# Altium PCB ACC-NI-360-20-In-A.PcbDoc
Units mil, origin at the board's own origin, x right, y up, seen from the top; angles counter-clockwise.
Board outline 1500 x 3250 mil, 2 copper layers (Top Layer, Bottom Layer), stack 22.756 mil thick; 18 components, 5 nets, 48 pads, 384 vias.
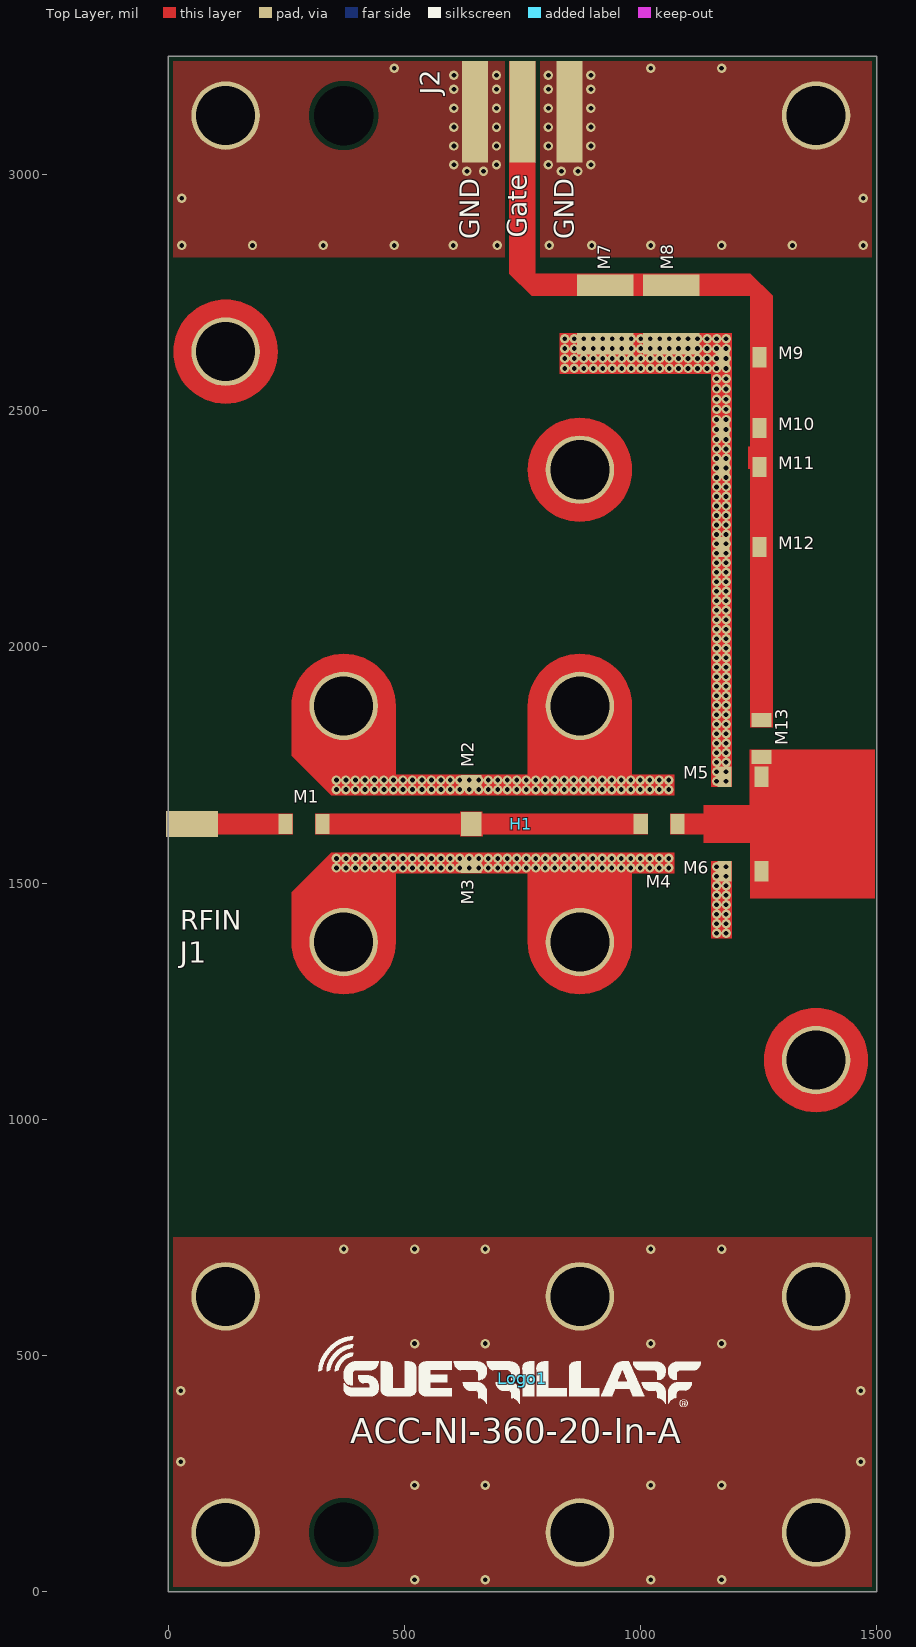
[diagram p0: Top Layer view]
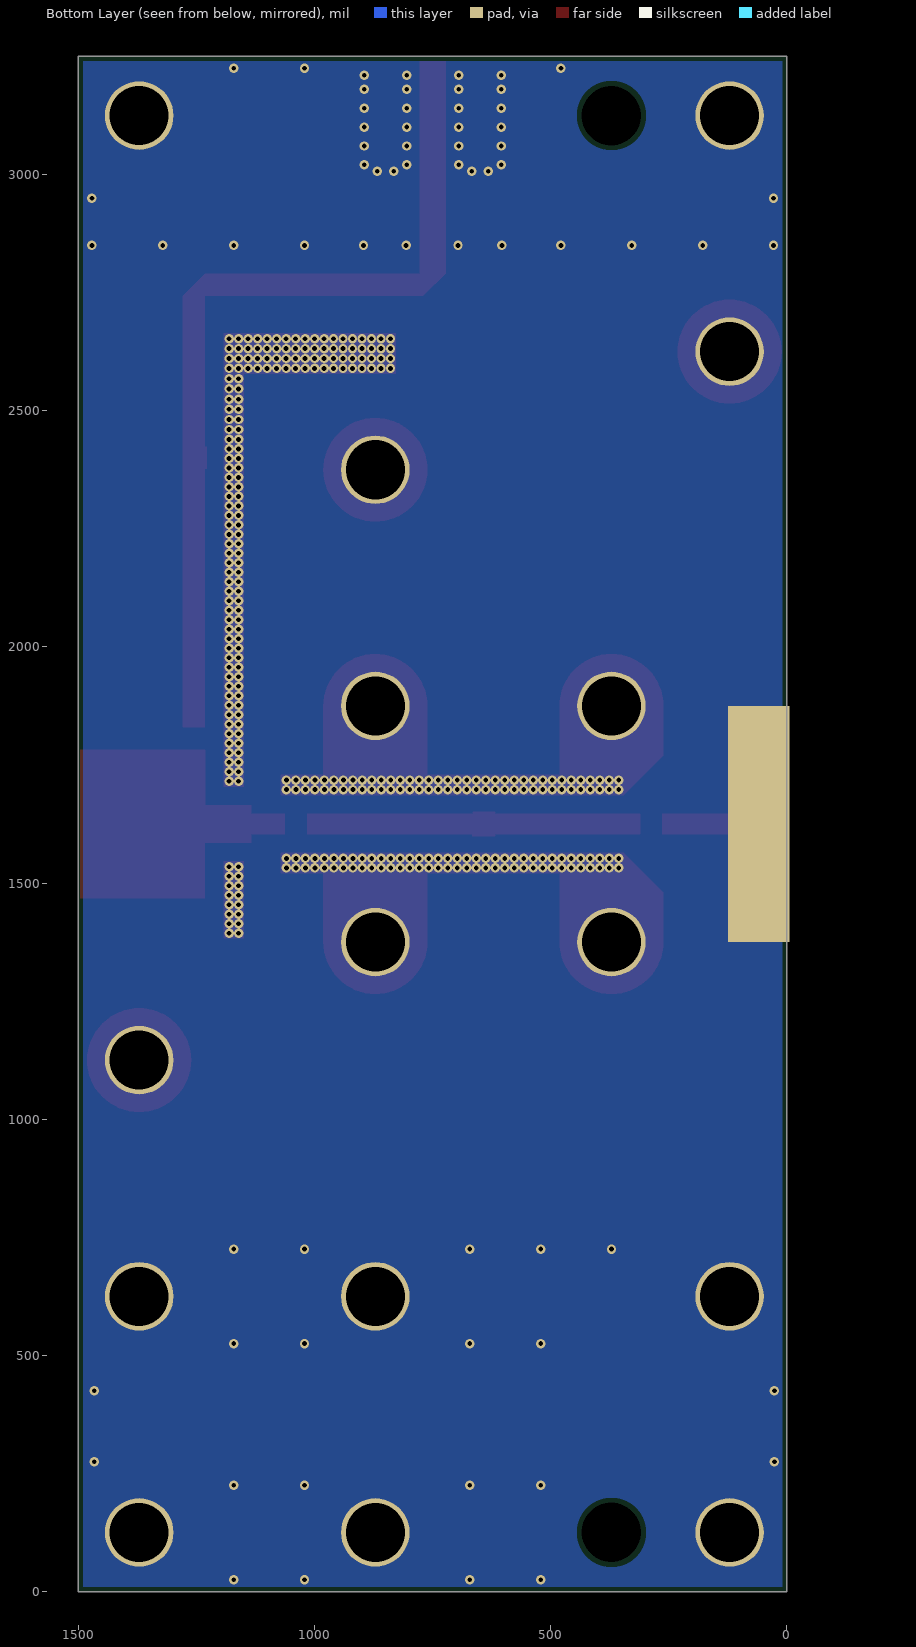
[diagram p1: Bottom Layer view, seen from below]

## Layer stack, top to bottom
Top Layer: signal copper 1.378
Dielectric 1: prepreg 20, RO4350B, Dk 3.48
Bottom Layer: signal copper 1.378

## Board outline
0,0 0,3250 1500,3250 1500,0

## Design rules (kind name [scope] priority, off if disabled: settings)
BackDrilling [IsVia and not InNet('GND')] p1: maxstublength=5 usetopbackdrill=TRUE usebottombackdrill=TRUE holeoversize=10 holetolplus=0.2 holetolminus=0.2
BoardOutlineClearance BoardOutlineClearance_Solder_Mask [OnLayer('Top Solder') Or OnLayer('Bottom Solder')] p1: gap=0 ignorepadtopadclearanceinfootprint=FALSE
BoardOutlineClearance [All] p2: gap=10 ignorepadtopadclearanceinfootprint=FALSE
Clearance Clearance_I/O [InNetClass('I/O') vs InNet('GND')] p1: gap=7 ignorepadtopadclearanceinfootprint=TRUE
Clearance Clearance_RF_Strip [InNetClass('RF_Strip') vs InNet('GND')] p2: gap=40 ignorepadtopadclearanceinfootprint=TRUE
Clearance Clearance_RF_15-15-8 [InNetClass('RF_15-15-8') vs InNet('GND')] p3: gap=15 ignorepadtopadclearanceinfootprint=TRUE
Clearance Clearance_RF_20-10-12 [InNetClass('RF_20-10-12') vs InNet('GND')] p4: gap=10 ignorepadtopadclearanceinfootprint=TRUE
Clearance Clearance_RF_30-20-16 [InNetClass('RF_30-20-16') vs InNet('GND')] p5: gap=20 ignorepadtopadclearanceinfootprint=TRUE
Clearance Clearance_RF_28-21-16_FR4 [InNetClass('RF_28-21-16_FR4') vs InNet('GND')] p6: gap=21 ignorepadtopadclearanceinfootprint=TRUE
Clearance Clearance_RF_15-27p5-8 [InNetClass('RF_15-27p5-8') vs InNet('GND')] p7: gap=27.5 ignorepadtopadclearanceinfootprint=TRUE
Clearance Clearance_RF_25-22-40_75ohm [InNetClass('RF_25-22-40_75ohm') vs InNet('GND')] p8: gap=22 ignorepadtopadclearanceinfootprint=TRUE
Clearance Clearance_GND [InNet('GND')] p9: gap=10 ignorepadtopadclearanceinfootprint=TRUE
Clearance [All] p10: gap=6 ignorepadtopadclearanceinfootprint=TRUE
ComponentClearance ComponentClearance_Heatsink [InComponent('All') And OnLayer('Top Layer') vs HasFootprint('Heatsink_wFid')] p1: gap=0 collisioncheckmode=3 verticalgap=0 showdistances=FALSE
ComponentClearance ComponentClearance_PCB_Frame [InComponent('All') And OnLayer('Top Layer') vs HasFootprint('PCB_Frame')] p2: gap=0 collisioncheckmode=3 verticalgap=0 showdistances=FALSE
ComponentClearance [All] p3: gap=10 collisioncheckmode=3 verticalgap=10 showdistances=TRUE
HoleSize [All] p1: absolutevalues=TRUE maxlimit=200 minlimit=8 maxpercent=80.000 minpercent=20.000
MinimumSolderMaskSliver [All] p1: minsoldermaskwidth=5
PlaneClearance [Not InNet('GND')] p1: clearance=20
PlaneConnect [InNet('GND')] p1: planeconnectstyle=Direct reliefexpansion=20 reliefentries=4 reliefconductorwidth=10 reliefairgap=10
PolygonConnect [All vs InNet('GND')] p1: connectstyle=Direct reliefconductorwidth=10 reliefentries=4 polygonreliefangle="90 Angle" airgapwidth=10
RoutingVias [All] p1: holewidth=10 width=20 viastyle="Through Hole" minholewidth=8 minwidth=18 maxholewidth=23.62 maxwidth=33.62
SilkToSilkClearance [All] p1: silktosilkclearance=5
SilkToSolderMaskClearance [IsPad] p1: minsilkscreentomaskgap=5 clearancetoexposedcopper=TRUE
SolderMaskExpansion [All] p1: expansion=1 istentingtop=FALSE
UnRoutedNet [All] p1: checkbadconnections=TRUE
Width [All] p1: maxlimit=100 minlimit=6 preferedwidth=10
22 further rules are at their usual default settings.

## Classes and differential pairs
component class ACC-NI-360-20-In-A: H1 J1 J2 Logo1 M1 M2 M3 M4 M5 M6 M7 M8 M9 M10 M11 M12 M13
net class RF_Strip: NetJ1_1 NetM1_1 NetM4_1

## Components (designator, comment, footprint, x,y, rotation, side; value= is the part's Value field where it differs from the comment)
F66 "Comment" PCB_Fab_30T-20G-16D_4003 -723.18,126.8 r0 top locked
H1 "Cooling_Block_Grid" Cooling_Block_Grid 1871.5,1625 r0 top locked
J1 "SMA Panel Mount_RevB" "SMA Panel Mount_RevB" 0,1625 r0 top
J2 "Header_H_3-Pin_100mil" Header_H_3-Pin_100mil 750,3250 r0 top
Logo1 "GRF_2021_Full" GRF_2021_Full 750,450 r0 top
M1 "0805_30x70x42" 0805_30x70x42#1 287.4,1625 r180 top
M2 "0805_30x70x42" 0805_30x70x42#1 641.73,1674.31 r270 top
M3 "0805_30x70x42" 0805_30x70x42#1 641.73,1575.69 r90 top
M4 "0805_30x70x42" 0805_30x70x42#1 1039.37,1625 r180 top
M5 "0805_30x70x42" 0805_30x70x42#2 1216.91,1725.24 r0 top
M6 "0805_30x70x42" 0805_30x70x42#2 1216.91,1524.76 r0 top
M7 "1210_45x120x75" 1210_45x120x75 925.04,2703.68 r90 top
M8 "1210_45x120x75" 1210_45x120x75 1064.96,2703.68 r90 top
M9 "0805_30x70x42" 0805_30x70x42#1 1212.6,2613.19 r0 top
M10 "0805_30x70x42" 0805_30x70x42#1 1212.6,2463.58 r0 top
M11 "0805_30x70x42" 0805_30x70x42#1 1212.6,2380.91 r0 top
M12 "0805_30x70x42" 0805_30x70x42#1 1212.6,2211.61 r0 top
M13 "0805_30x70x42" 0805_30x70x42#1 1255.91,1806.1 r90 top

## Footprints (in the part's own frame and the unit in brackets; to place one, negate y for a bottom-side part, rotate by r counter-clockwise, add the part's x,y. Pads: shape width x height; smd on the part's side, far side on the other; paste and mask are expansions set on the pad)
0805_30x70x42#1 [mil] "Generic 0805 SMD"
  rect 30x43 smd: 1(-39,0) 2(39,0)
0805_30x70x42#2 [mil] "Generic 0805 SMD"
  rect 30x43 smd: 1(-39,0)
  rect 30x43 smd mask+1: 2(39,0)
1210_45x120x75 [mil] "Generic 1210 SMD"
  rect 45x120 smd: 1(-62,0) 2(62,0)
Cooling_Block_Grid [mil] "Heatsink Mounting Holes"
  round 145 hole 125 paste-100 mask+37.5: 1(-1750,-1500) 1(-1750,-1000) 1(-1750,1000) 1(-1750,1500) 1(-1500,-250) 1(-1500,250) 1(-1000,-1500) 1(-1000,-1000) 1(-1000,-250) 1(-1000,250) 1(-1000,750) 1(-500,-1500) 1(-500,-1000) 1(-500,-500) 1(-500,1500)
  round 0 hole 125.98 unplated paste-100 mask+20: 2(-1500,-1500) 2(-1500,1500)
GRF_2021_Full [mil] "2021 Guerrilla RF Logo"
  silkscreen extent -432,-59 378,90
Header_H_3-Pin_100mil [mil] "Generic Flat Header"
  rect 55x215 smd paste-28: 1(-100,-117.5) 2(0,-117.5) 3(100,-117.5)
PCB_Fab_30T-20G-16D_4003 [mil] "STD RF&Stack  30mil RF 20mil Gap  16mil Dielectric"
"SMA Panel Mount_RevB" [mil] "901-2GB100000AE"
  rect 110x55 smd paste-50: 1(50,0)
  rect 130x500 smd far side paste-50: 2(60,0)

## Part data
H1: library part "Mounting Holes"
J1: library part RF_Conn
J2: library part Header_3-Pin, "Header 3-Pin"
Logo1: library part GRF_Logo, "=CurrentFootprint"
M1 M2 M3 M4 M5 M6 M7 M8 M9 M10 M11 M12: library part Capacitor
M13: library part Resistor

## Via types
v1: diameter 20/20 (per signal layer), hole 10, Top Layer to Bottom Layer, tented top, 318 vias
v2: diameter 20/20 (per signal layer), hole 10, Top Layer to Bottom Layer, 66 vias

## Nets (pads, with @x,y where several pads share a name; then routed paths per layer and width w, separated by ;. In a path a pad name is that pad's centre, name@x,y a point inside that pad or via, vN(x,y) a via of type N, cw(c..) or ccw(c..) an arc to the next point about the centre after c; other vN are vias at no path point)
GND: H1.1 J1.2 J2.1 J2.3 M2.1 M3.1 M5.1 M6.1 M7.1 M8.1 M9.1 M10.1 M11.1 M12.1
  other v1: 1161,1393.75 1181.1,1393.75 1161,1413.85 1181.1,1413.85 1161,1433.95 1181.1,1433.95 1161,1454.05 1181.1,1454.05 1161,1474.15 1181.1,1474.15 1161,1494.25 1181.1,1494.25 1161,1514.35 1181.1,1514.35 356.2,1532.07 376.3,1532.07 396.4,1532.07 416.5,1532.07 436.6,1532.07 456.7,1532.07 476.8,1532.07 496.9,1532.07 517,1532.07 537.1,1532.07 557.2,1532.07 577.3,1532.07 597.4,1532.07 617.5,1532.07 637.6,1532.07 657.7,1532.07 677.8,1532.07 697.9,1532.07 718,1532.07 738.1,1532.07 758.2,1532.07 778.3,1532.07 798.4,1532.07 818.5,1532.07 838.6,1532.07 858.7,1532.07 878.8,1532.07 898.9,1532.07 919,1532.07 939.1,1532.07 959.2,1532.07 979.3,1532.07 999.4,1532.07 1019.5,1532.07 1039.6,1532.07 1059.7,1532.07 1161,1534.45 1181.1,1534.45 356.2,1552.17 376.3,1552.17 396.4,1552.17 416.5,1552.17 436.6,1552.17 456.7,1552.17 476.8,1552.17 496.9,1552.17 517,1552.17 537.1,1552.17 557.2,1552.17 577.3,1552.17 597.4,1552.17 617.5,1552.17 637.6,1552.17 657.7,1552.17 677.8,1552.17 697.9,1552.17 718,1552.17 738.1,1552.17 758.2,1552.17 778.3,1552.17 798.4,1552.17 818.5,1552.17 838.6,1552.17 858.7,1552.17 878.8,1552.17 898.9,1552.17 919,1552.17 939.1,1552.17 959.2,1552.17 979.3,1552.17 999.4,1552.17 1019.5,1552.17 1039.6,1552.17 1059.7,1552.17 356.2,1697.83 376.3,1697.83 396.4,1697.83 416.5,1697.83 436.6,1697.83 456.7,1697.83 476.8,1697.83 496.9,1697.83 517,1697.83 537.1,1697.83 557.2,1697.83 577.3,1697.83 597.4,1697.83 617.5,1697.83 637.6,1697.83 657.7,1697.83 677.8,1697.83 697.9,1697.83 718,1697.83 738.1,1697.83 758.2,1697.83 778.3,1697.83 798.4,1697.83 818.5,1697.83 838.6,1697.83 858.7,1697.83 878.8,1697.83 898.9,1697.83 919,1697.83 939.1,1697.83 959.2,1697.83 979.3,1697.83 999.4,1697.83 1019.5,1697.83 1039.6,1697.83 1059.7,1697.83 1161,1715.55 1181.1,1715.55 356.2,1717.93 376.3,1717.93 396.4,1717.93 416.5,1717.93 436.6,1717.93 456.7,1717.93 476.8,1717.93 496.9,1717.93 517,1717.93 537.1,1717.93 557.2,1717.93 577.3,1717.93 597.4,1717.93 617.5,1717.93 637.6,1717.93 657.7,1717.93 677.8,1717.93 697.9,1717.93 718,1717.93 738.1,1717.93 758.2,1717.93 778.3,1717.93 798.4,1717.93 818.5,1717.93 838.6,1717.93 858.7,1717.93 878.8,1717.93 898.9,1717.93 919,1717.93 939.1,1717.93 959.2,1717.93 979.3,1717.93 999.4,1717.93 1019.5,1717.93 1039.6,1717.93 1059.7,1717.93 1161,1735.65 1181.1,1735.65 1161,1755.75 1181.1,1755.75 1161,1775.85 1181.1,1775.85 1161,1795.95 1181.1,1795.95 1161,1816.05 1181.1,1816.05 1161,1836.15 1181.1,1836.15 1161,1856.25 1181.1,1856.25 1161,1876.35 1181.1,1876.35 1161,1896.45 1181.1,1896.45 1161,1916.55 1181.1,1916.55 1161,1936.65 1181.1,1936.65 1161,1956.75 1181.1,1956.75 1161,1976.85 1181.1,1976.85 1161,1996.95 1181.1,1996.95 1161,2017.05 1181.1,2017.05 1161,2037.15 1181.1,2037.15 1161,2057.25 1181.1,2057.25 1161,2077.35 1181.1,2077.35 1161,2097.45 1181.1,2097.45 1161,2117.55 1181.1,2117.55 1161,2137.65 1181.1,2137.65 1161,2157.75 1181.1,2157.75 1161,2177.85 1181.1,2177.85 1161,2197.95 1181.1,2197.95 1161,2218.05 1181.1,2218.05 1161,2238.15 1181.1,2238.15 1161,2258.25 1181.1,2258.25 1161,2278.35 1181.1,2278.35 1161,2298.45 1181.1,2298.45 1161,2318.55 1181.1,2318.55 1161,2338.65 1181.1,2338.65 1161,2358.75 1181.1,2358.75 1161,2378.85 1181.1,2378.85 1161,2398.95 1181.1,2398.95 1161,2419.05 1181.1,2419.05 1161,2439.15 1181.1,2439.15 1161,2460.25 1181.1,2460.25 1161,2481.35 1181.1,2481.35 1161,2502.95 1181.1,2502.95 1161,2524.55 1181.1,2524.55 1161,2546.15 1181.1,2546.15 1161,2567.75 1181.1,2567.75 839.4,2589.57 859.5,2589.57 879.6,2589.57 899.7,2589.57 919.8,2589.57 939.9,2589.57 960,2589.57 980.1,2589.57 1000.2,2589.57 1020.3,2589.57 1040.4,2589.57 1060.5,2589.57 1080.6,2589.57 1100.7,2589.57 1120.8,2589.57 1140.9,2589.57 1161,2589.57 1181.1,2589.57 839.4,2610.56 859.5,2610.56 879.6,2610.56 899.7,2610.56 919.8,2610.56 939.9,2610.56 960,2610.56 980.1,2610.56 1000.2,2610.56 1020.3,2610.56 1040.4,2610.56 1060.5,2610.56 1080.6,2610.56 1100.7,2610.56 1120.8,2610.56 1140.9,2610.56 1161,2610.56 1181.1,2610.56 839.4,2631.56 859.5,2631.56 879.6,2631.56 899.7,2631.56 919.8,2631.56 939.9,2631.56 960,2631.56 980.1,2631.56 1000.2,2631.56 1020.3,2631.56 1040.4,2631.56 1060.5,2631.56 1080.6,2631.56 1100.7,2631.56 1120.8,2631.56 1140.9,2631.56 1161,2631.56 1181.1,2631.56 839.4,2652.56 859.5,2652.56 879.6,2652.56 899.7,2652.56 919.8,2652.56 939.9,2652.56 960,2652.56 980.1,2652.56 1000.2,2652.56 1020.3,2652.56 1040.4,2652.56 1060.5,2652.56 1080.6,2652.56 1100.7,2652.56 1120.8,2652.56 1140.9,2652.56 1161,2652.56 1181.1,2652.56
  other v2: 521.5,25 671.5,25 1021.5,25 1171.5,25 521.5,225 671.5,225 1021.5,225 1171.5,225 26.5,275 1466.5,275 26.5,425 1466.5,425 521.5,525 671.5,525 1021.5,525 1171.5,525 371.5,725 521.5,725 671.5,725 1021.5,725 1171.5,725 28.5,2850 178.5,2850 328.5,2850 478.5,2850 603.5,2850 696.5,2850 806.5,2850 896.5,2850 1021.5,2850 1171.5,2850 1321.5,2850 1471.5,2850 28.5,2950 1471.5,2950 632.5,3007 667.5,3007 832.5,3007 867.5,3007 605,3020.5 695,3020.5 805,3020.5 895,3020.5 605,3060.5 695,3060.5 805,3060.5 895,3060.5 605,3100.5 695,3100.5 805,3100.5 895,3100.5 605,3140.5 695,3140.5 805,3140.5 895,3140.5 605,3180.5 695,3180.5 805,3180.5 895,3180.5 605,3210.5 695,3210.5 805,3210.5 895,3210.5 478.5,3225 1021.5,3225 1171.5,3225
NetJ1_1: J1.1 M1.2
NetJ2_2: J2.2 M7.2 M8.2 M9.2 M10.2 M11.2 M12.2 M13.2
NetM1_1: M1.1 M2.2 M3.2 M4.2
NetM4_1: M4.1 M5.2 M6.2 M13.1
pads on no net: H1.2

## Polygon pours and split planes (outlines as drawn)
GND on Top Layer "NONET_L-01_P-001" (solid, pour order 0): 0,750 1500,750 1500,0 0,0
GND on Top Layer "NONET_L-01_P-001" (solid, pour order 4): 0,3250 1500,3250 1500,2825 0,2825
no net on Bottom Solder "NONET_L-01_P-001" (solid): 0,3250 0,0 1500,0 1500,3250
no net on Top Solder "NONET_L-01_P-001" (solid): 0,3250 0,0 1500,0 1500,3250
GND on Bottom Layer "NONET_L-01_P-001" (solid, pour order 2): 0,3250 0,0 1500,0 1500,3250

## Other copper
Top Layer:
  region net GND: 231.5,2625 ccw(c121.5,2625) 121.5,2735 ccw(c121.5,2625) 11.5,2625 ccw(c121.5,2625) 121.5,2515 ccw(c121.5,2625)
  region net GND: 981.5,2375 ccw(c871.5,2375) 871.5,2485 ccw(c871.5,2375) 761.5,2375 ccw(c871.5,2375) 871.5,2265 ccw(c871.5,2375)
  region net GND: 1371.5,1015 ccw(c1371.5,1125) 1481.5,1125 ccw(c1371.5,1125) 1371.5,1235 ccw(c1371.5,1125) 1261.5,1125 ccw(c1371.5,1125)
  region net GND: 371.5,1485 ccw(c371.5,1375) 261.5,1375 ccw(c371.5,1375) 371.5,1265 ccw(c371.5,1375) 481.5,1375 ccw(c371.5,1375)
  region net GND: 371.5,1985 ccw(c371.5,1875) 261.5,1875 ccw(c371.5,1875) 371.5,1765 ccw(c371.5,1875) 481.5,1875 ccw(c371.5,1875)
  region net GND: 761.5,1875 ccw(c871.5,1875) 871.5,1765 ccw(c871.5,1875) 981.5,1875 ccw(c871.5,1875) 871.5,1985 ccw(c871.5,1875)
  region net GND: 981.5,1375 ccw(c871.5,1375) 871.5,1485 ccw(c871.5,1375) 761.5,1375 ccw(c871.5,1375) 871.5,1265 ccw(c871.5,1375)
  region net GND: 345.5,1686.02 261.5,1770.02 261.5,1875 481.5,1875 481.5,1686.02
  region net GND: 345.5,1563.98 261.5,1479.98 261.5,1375 481.5,1375 481.5,1563.98
  region net GND: 761.5,1875 761.5,1717.93 981.5,1717.93 981.5,1875
  region net GND: 981.5,1375 981.5,1532.07 761.5,1532.07 761.5,1375
  region net NetJ2_2: 722.5,3240 722.5,2790.35 769.74,2743.11 811.5,2743.11 811.5,2790.35 777.5,2790.35 777.5,3240
  region net NetJ2_2: 807.5,2790.35 1232.28,2790.35 1279.53,2743.11 1279.53,1830.1 1232.28,1830.1 1232.28,2376.83 1228.49,2376.83 1228.35,2376.97 1228.35,2424.21 1232.28,2424.21 1232.28,2743.11 807.5,2743.11
  region net GND: 1149.61,1546.26 1149.61,1383 1192.91,1383 1192.91,1546.26
  region net GND: 828.5,2664.37 828.5,2577.76 1149.61,2577.76 1149.61,1865.16 1192.91,1865.16 1192.91,2664.37
  region net GND: 1149.61,1703.74 1149.61,1865.16 1192.91,1865.16 1192.91,1703.74
  region net GND: 345.5,1563.98 1071.51,1563.98 1071.51,1520.67 345.5,1520.67
  region net GND: 345.5,1686.02 1071.51,1686.02 1071.51,1729.33 345.5,1729.33
  region net NetJ1_1: 263.78,1646.5 0,1646.5 0,1603.5 263.78,1603.5
  region net NetM1_1: 1015.75,1646.5 665.35,1646.5 665.35,1650.59 618.11,1650.59 618.11,1646.5 311.02,1646.5 311.02,1603.5 618.11,1603.5 618.11,1599.41 666.34,1599.41 666.34,1603.5 1015.75,1603.5
  region net NetM4_1: 1062.99,1646.5 1133.86,1646.5 1133.86,1664.37 1231.3,1664.37 1231.3,1782.48 1496,1782.48 1496,1467.52 1232.28,1467.52 1232.28,1585.63 1133.86,1585.63 1133.86,1603.5 1062.99,1603.5

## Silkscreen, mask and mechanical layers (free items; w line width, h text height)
Top Overlay:
  text "Gate" at 772.42,2866.01 h70 r90
  text "GND" at 672.42,2863.42 h70 r90
  text "GND" at 872.42,2863.42 h70 r90
  text "RFIN" at 25,1387.58 h70
  text "ACC-NI-360-20-In-A" at 385.06,296.18 h90
Top Solder:
  region: 1271.65,2638.78 1228.35,2638.78 1228.35,2587.6 1271.65,2587.6
  rectangle: 1153.54,2587.6 1196.85,2638.78
  region: 1271.65,2489.17 1228.35,2489.17 1228.35,2437.99 1271.65,2437.99
  rectangle: 1153.54,2437.99 1196.85,2489.17
  region: 1271.65,2406.5 1228.35,2406.5 1228.35,2355.32 1271.65,2355.32
  rectangle: 1153.54,2355.32 1196.85,2406.5
  region: 1271.65,2237.2 1228.35,2237.2 1228.35,2186.02 1271.65,2186.02
  rectangle: 1153.54,2186.02 1196.85,2237.2
  region: 1281.5,1747.05 1281.5,1790.35 1230.32,1790.35 1230.32,1747.05
  region: 1230.32,1865.16 1230.32,1821.85 1281.5,1821.85 1281.5,1865.16
  rectangle: 980.32,1599.41 1023.62,1650.59
  region: 1098.43,1650.59 1055.12,1650.59 1055.12,1599.41 1098.43,1599.41
  region: 616.14,1733.36 616.14,1690.06 667.32,1690.06 667.32,1733.36
  region: 667.32,1615.25 667.32,1658.56 616.14,1658.56 616.14,1615.25
  region: 616.14,1634.75 616.14,1591.44 667.32,1591.44 667.32,1634.75
  region: 667.32,1516.64 667.32,1559.95 616.14,1559.95 616.14,1516.64
  region: 346.46,1650.59 303.15,1650.59 303.15,1599.41 346.46,1599.41
  rectangle: 228.35,1599.41 271.65,1650.59
  pour cut-out: 1371.5,2443.58 1371.5,2483.58 1284.96,2483.58 1284.96,2443.58
  pour cut-out: 1371.5,2360.91 1371.5,2400.91 1284.96,2400.91 1284.96,2360.91
  pour cut-out: 1371.5,2191.61 1371.5,2231.61 1284.96,2231.61 1284.96,2191.61
  pour cut-out: 1351.5,2593.19 1351.5,2633.19 1284.96,2633.19 1284.96,2593.19
  pour cut-out: 621.49,1740 661.49,1740 661.49,1805 621.49,1805
  pour cut-out: 661.5,1510 621.5,1510 621.5,1445 661.5,1445
  pour cut-out: 316.5,1654.76 316.5,1695 261.5,1695 261.5,1654.76
  pour cut-out: 1146.5,1504.52 1146.5,1544.52 1081.5,1544.52 1081.5,1504.52
  pour cut-out: 171.5,1445 0,1445 0,1305 171.5,1305
  pour cut-out: 1066.5,1515 1001.5,1515 1001.5,1475 1066.5,1475
  pour cut-out: 1326.5,1785 1326.5,1873.03 1286.5,1873.03 1286.5,1785
  pour cut-out: 0,0 0,775 1500,775 1500,0
  pour cut-out: 1500,3250 1500,2798.18 0,2798.18 0,3250
  pour cut-out: 1136,2798.18 1136,2604 994.96,2604 994.96,2798.18
  pour cut-out: 995.04,2798.18 995.04,2604 853,2604 853,2798.18
  pour cut-out: 1146.5,1705 1146.5,1745 1081.5,1745 1081.5,1705
  pour cut-out: 1222.44,1739.17 1289.37,1739.17 1289.37,1873.03 1222.44,1873.03
  pour cut-out: 972.44,1658.46 972.44,1591.54 1106.3,1591.54 1106.3,1658.46
  pour cut-out: 220.47,1658.46 220.47,1591.54 354.33,1591.54 354.33,1658.46
Board_Dimension:
  the board outline again, w10
Drill Drawing:
  lines w15: -1658.9,-2648.2 3415.71,-2648.2 ; -1658.9,-2198.2 3415.71,-2198.2 ; -1108.02,-2798.2 -1108.02,-2048.2 ; -518.18,-2798.2 -518.18,-2048.2 ; 631.49,-2798.2 631.49,-2048.2 ; 1137.36,-2798.2 1137.36,-2048.2 ; 1871.16,-2798.2 1871.16,-2048.2 ; -1658.9,-2798.2 3415.71,-2798.2 3415.71,-2048.2 -1658.9,-2048.2 -1658.9,-2798.2
  text "Symbol" at -1568.9,-2153.2 h72
  text "Count" at -1063.02,-2153.2 h72
  text "Hole Size" at -473.18,-2153.2 h72
  text "Plated" at 676.49,-2153.2 h72
  text "Hole Type" at 1182.36,-2153.2 h72
  text "Drill Layer Pair" at 1916.16,-2153.2 h72
  text "384" at -1063.02,-2303.2 h60
  text "10.00mil (0.254mm)" at -473.18,-2303.2 h60
  text "PTH" at 676.49,-2303.2 h60
  text "Round" at 1182.36,-2303.2 h60
  text "Top Layer - Bottom Layer" at 1916.16,-2303.2 h60
  text "B" at -1597.99,-2313.19 h66.67
  text "15" at -1063.02,-2453.2 h60
  text "125.00mil (3.175mm)" at -473.18,-2453.2 h60
  text "PTH" at 676.49,-2453.2 h60
  text "Round" at 1182.36,-2453.2 h60
  text "Top Layer - Bottom Layer" at 1916.16,-2453.2 h60
  text "H" at -1597.99,-2463.19 h66.67
  text "2" at -1063.02,-2603.2 h60
  text "125.98mil (3.200mm)" at -473.18,-2603.2 h60
  text "NPTH" at 676.49,-2603.2 h60
  text "Round" at 1182.36,-2603.2 h60
  text "Top Layer - Bottom Layer" at 1916.16,-2603.2 h60
  text "N" at -1597.99,-2613.19 h66.67
  text "401 Total" at -1063.02,-2753.2 h60
Document:
  lines w10: -428.3,1936.8 -78.3,1636.8 ; -260,390 285,220 ; -53.3,1386.8 -78.3,1386.8 -78.3,1886.8 -53.3,1886.8 ; 196.28,1634.94 -450,2600 ; 487.95,1627.64 -450,2600 ; 834.72,1618.97 -450,2600 ; 282.96,22.67 882.96,22.67 882.96,222.67 282.96,222.67 282.96,22.67

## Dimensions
0,0 to 0,3250 on Mechanical 16
0,0 to 1500,0 on Mechanical 16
